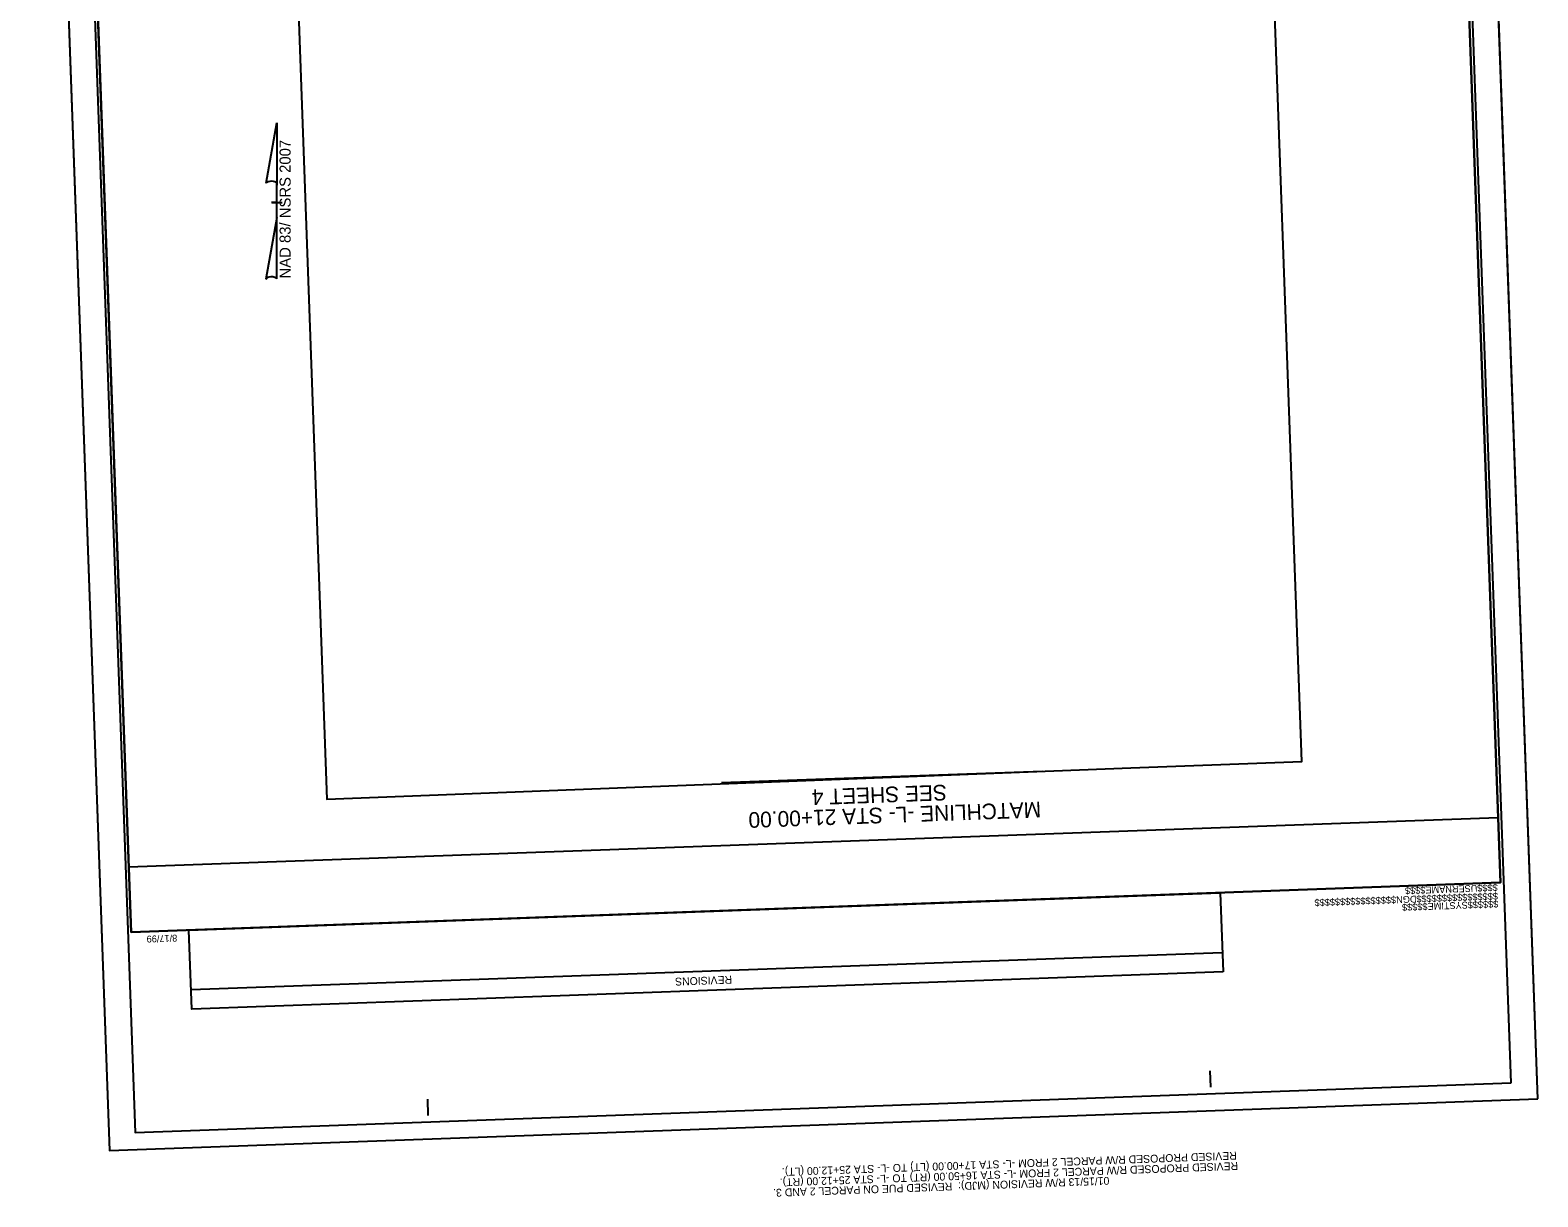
# Model space of a CAD drawing. Extents: x 2065256 to 2066537, y 145527 to 147314.
# Drawn here: x 2065382 to 2066537, y 145527 to 146420 of the extents above; entities that cross this region are included whole.
import ezdxf

# ---------------------------------------------------------------- set-up
doc = ezdxf.new("R2010")
doc.units = 0
for name, color, linetype in [('Matchline', 7, 'Continuous'), ('Matchline Text', 7, 'Continuous'), ('Prop North Arrow NAD83 for Plan Sheets CELL', 7, 'Continuous'), ('Sheet Block Revision CELL', 7, 'Continuous'), ('Sheet Clip Boundary CELL', 7, 'Continuous'), ('Sheet Cutting Line CELL', 7, 'Continuous'), ('Sheet Layout Plan Border', 7, 'Continuous'), ('Sheet Plan CELL', 7, 'Continuous'), ('Sheet Plan Layout CELL', 7, 'Continuous'), ('Sheet Plot Border Inside CELL', 7, 'Continuous'), ('Sheet Plot Border Outside CELL', 7, 'Continuous')]:
    doc.layers.add(name, color=color, linetype=linetype)

msp = doc.modelspace()

# ---------------------------------------------------------------- linework, layer by layer
at = {"layer": 'Matchline'}
msp.add_line((2065911.5, 145844), (2066157.6, 145852.9), dxfattribs=at)
at = {"layer": 'Prop North Arrow NAD83 for Plan Sheets CELL'}
for p, q in [((2065562.7, 146303.1), (2065570.9, 146349.4)), ((2065571, 146349.4), (2065570.9, 146349.4)), ((2065571, 146349.4), (2065570.9, 146349.4)), ((2065571, 146349.4), (2065571, 146301.6)), ((2065571, 146276.8), (2065571, 146303)), ((2065571, 146301.6), (2065571, 146303)), ((2065567, 146288.4), (2065566.9, 146288.4)), ((2065567, 146288.4), (2065575, 146288.4)), ((2065570.5, 146288.4), (2065567, 146288.4)), ((2065571, 146276.8), (2065562.6, 146229.6)), ((2065571, 146229.8), (2065571, 146276.8))]:
    msp.add_line(p, q, dxfattribs=at)
for centre, start_param, end_param in [((2065566.8, 146302.6), 0.216388, 2.908219), ((2065566.8, 146229.4), 0.201328, 3.141593)]:
    msp.add_ellipse(centre, major_axis=(4.23, -0.03), ratio=0.461098, start_param=start_param, end_param=end_param, dxfattribs=at)
at = {"layer": 'Sheet Block Revision CELL'}
msp.add_line((2066295.3, 145713.7), (2065505.2, 145685.2), dxfattribs=at)
msp.add_lwpolyline([(2066295.9, 145699.2), (2065505.7, 145670.6), (2065503.5, 145731.1), (2066293.7, 145759.7)], close=True, dxfattribs=at)
at = {"layer": 'Sheet Clip Boundary CELL'}
msp.add_lwpolyline([(2066225.3, 145855.3), (2066356.3, 145860.1), (2066306.2, 147244.4), (2065582.2, 147218.2), (2065589.9, 147003.5), (2065567, 147001.1), (2065609.3, 145831.4)], close=True, dxfattribs=at)
at = {"layer": 'Sheet Cutting Line CELL'}
for p, q in [((2066537, 145601.9), (2066476.2, 147284.3)), ((2065381.9, 147244.7), (2065442.7, 145562.3)), ((2065442.7, 145562.3), (2066537, 145601.9))]:
    msp.add_line(p, q, dxfattribs=at)
at = {"layer": 'Sheet Layout Plan Border'}
msp.add_lwpolyline([(2066506.7, 145817.4), (2066456.1, 147216.5), (2065618.2, 147186.2), (2065625, 146997.1), (2065413.7, 146989.4), (2065457.4, 145779.5)], close=True, dxfattribs=at)
at = {"layer": 'Sheet Plan CELL'}
for p, q in [((2066508.5, 145767.4), (2066508.5, 145767.4)), ((2065459.2, 145729.5), (2065459.2, 145729.5)), ((2066286.5, 145610.9), (2066286.1, 145623.3)), ((2065686.9, 145589.2), (2065686.5, 145601.7))]:
    msp.add_line(p, q, dxfattribs=at)
for points in [[(2065405, 147228.6), (2065459.2, 145729.5), (2066508.5, 145767.4), (2066454.3, 147266.5)], [(2066508.5, 145767.4), (2065459.2, 145729.5), (2065412.2, 147028.6), (2065562.2, 147034.1), (2065555, 147234), (2066454.3, 147266.5)]]:
    msp.add_lwpolyline(points, close=True, dxfattribs=at)
at = {"layer": 'Sheet Plan Layout CELL'}
msp.add_lwpolyline([(2065459.2, 145729.5), (2066508.5, 145767.4), (2066454.3, 147266.5), (2065616.4, 147236.2), (2065625, 146997.1), (2065413.7, 146989.4)], close=True, dxfattribs=at)
at = {"layer": 'Sheet Plot Border Inside CELL'}
msp.add_lwpolyline([(2066516.6, 145614.2), (2066456.4, 147279.1), (2065402.1, 147241), (2065462.3, 145576)], close=True, dxfattribs=at)
at = {"layer": 'Sheet Plot Border Outside CELL'}
msp.add_lwpolyline([(2066537, 145601.9), (2066476.2, 147284.3), (2065381.9, 147244.7), (2065442.7, 145562.3)], close=True, dxfattribs=at)

# ---------------------------------------------------------------- texts
at = {"layer": 'Matchline Text'}
for s, p in [('SEE SHEET 4', (2066084, 145842.5)), ('MATCHLINE -L- STA 21+00.00', (2066156.2, 145829.4))]:
    msp.add_text(s, height=12, rotation=182.0702, dxfattribs=at).set_placement(p)
at = {"layer": 'Prop North Arrow NAD83 for Plan Sheets CELL'}
msp.add_text('NAD 83/ NSRS 2007', height=8.5, rotation=90, dxfattribs=at).set_placement((2065581.5, 146230.1))
at = {"layer": 'Sheet Block Revision CELL'}
for s, p in [('REVISIONS', (2065919.6, 145696.1)), ('                                                           REVISED PROPOSED R/W PARCEL 2 FROM -L- STA 17+00.00 (LT) TO -L- STA 25+12.00 (LT). ', (2066437.7, 145566.1)), ('                                                           REVISED PROPOSED R/W PARCEL 2 FROM -L- STA 16+50.00 (RT) TO -L- STA 25+12.00 (RT).', (2066438.7, 145558.2)), ('01/15/13 R/W REVISION (MJD):  REVISED PUE ON PARCEL 2 AND 3.', (2066208.6, 145542.1))]:
    msp.add_text(s, height=6, rotation=182.0702, dxfattribs=at).set_placement(p)
at = {"layer": 'Sheet Plan CELL'}
for s, p in [('$$$$USERNAME$$$$', (2066506.2, 145766.3)), ('$$$$$$$$$$$$$$$$DGN$$$$$$$$$$$$$$$$', (2066506.4, 145759.7)), ('$$$$$$SYSTIME$$$$$', (2066506.7, 145753.7)), ('8/17/99', (2065494.5, 145727.6))]:
    msp.add_text(s, height=5.25, rotation=182.0702, dxfattribs=at).set_placement(p)

doc.saveas('drawing.dxf')
